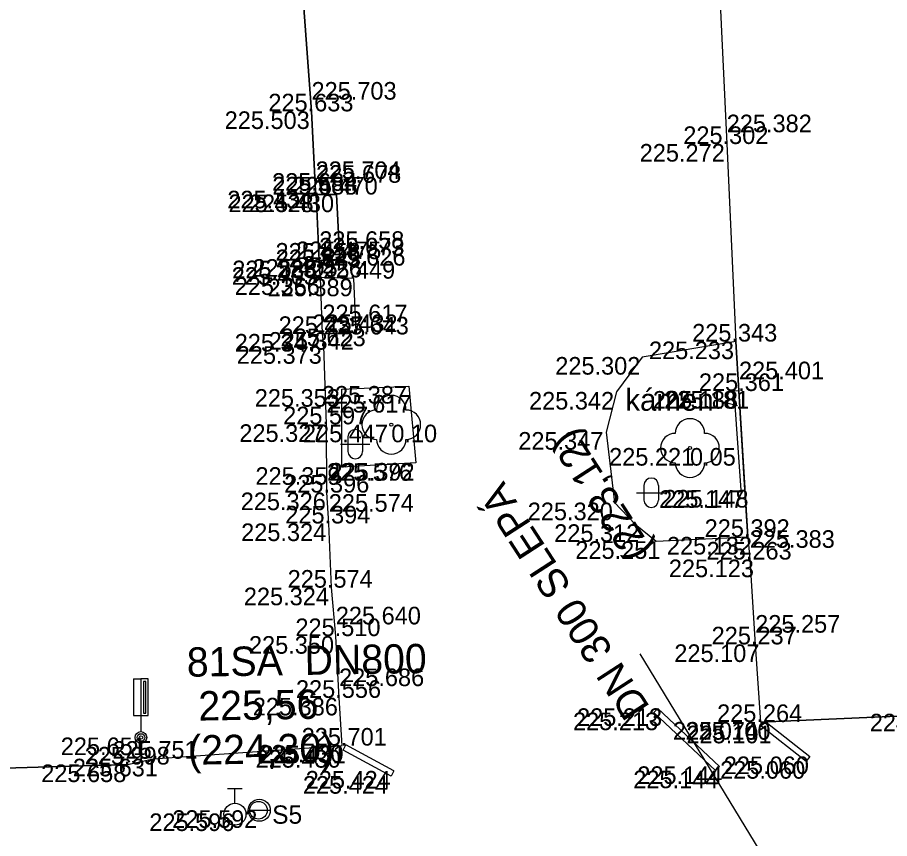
# Model space of a CAD drawing. Extents: x -599516 to -599132, y -1163668 to -1163119.
# Drawn here: x -599368.79 to -599353.92, y -1163367.41 to -1163353.41 of the extents above; entities that cross this region are included whole.
import ezdxf

# ---------------------------------------------------------------- set-up
doc = ezdxf.new("R2010")
doc.units = 0
for name, color, linetype in [('Bod-oznac1', 7, 'Continuous'), ('Bod-oznac2', 7, 'Continuous'), ('Bod-oznac3', 7, 'Continuous'), ('Bod-vyska1', 7, 'Continuous'), ('Bod-vyska2', 7, 'Continuous'), ('Bod-vyska3', 7, 'Continuous'), ('Z_cela-hrobu-dolni-linie', 7, 'Continuous'), ('Z_cela-hrobu-horni-linie', 7, 'Continuous'), ('Z_kanalizace-destova', 7, 'Continuous'), ('Z_komunikace', 7, 'Continuous'), ('Z_kultury-znacky', 7, 'Continuous'), ('Z_nove-stromy-prumer-kmene', 7, 'Continuous'), ('Z_obvod-skruze', 7, 'Continuous'), ('Z_obvod-skruze-cislo-foto', 7, 'Continuous'), ('Z_popis-budov-povrchu', 7, 'Continuous'), ('Z_stromy-nove-vysazene', 7, 'Continuous'), ('Z_voda-znacky-hydrant', 7, 'Continuous'), ('Z_vodovod-bez-rozliseni', 7, 'Continuous'), ('Z_vol-lin-obrubnik', 7, 'Continuous'), ('Z_vol-lin-odkazova-cara', 7, 'Continuous'), ('Z_znacky-ostatni-orientacni-sloupek', 7, 'Continuous'), ('Z_znacky-ostatni-skruz', 7, 'Continuous'), ('Z_zpevnene-plochy', 7, 'Continuous')]:
    doc.layers.add(name, color=color, linetype=linetype)

msp = doc.modelspace()

# ---------------------------------------------------------------- linework, layer by layer
at = {"layer": 'Bod-oznac1'}
for p, q in [((-599363.774, -1163355.013), (-599363.774, -1163355.013)), ((-599356.698, -1163355.569), (-599356.698, -1163355.569)), ((-599363.705, -1163356.366), (-599363.705, -1163356.366)), ((-599363.695, -1163356.43), (-599363.695, -1163356.43)), ((-599363.349, -1163356.43), (-599363.349, -1163356.43)), ((-599363.289, -1163357.532), (-599363.289, -1163357.532)), ((-599363.643, -1163357.669), (-599363.643, -1163357.669)), ((-599363.642, -1163357.557), (-599363.642, -1163357.557)), ((-599363.623, -1163357.842), (-599363.623, -1163357.842)), ((-599363.052, -1163357.864), (-599363.052, -1163357.864)), ((-599363.588, -1163358.807), (-599363.588, -1163358.807)), ((-599363.011, -1163358.775), (-599363.011, -1163358.775)), ((-599363.565, -1163359.015), (-599363.565, -1163359.015)), ((-599356.541, -1163358.936), (-599356.541, -1163358.936)), ((-599358.14, -1163359.2), (-599358.14, -1163359.2)), ((-599363.259, -1163359.747), (-599363.259, -1163359.747)), ((-599362.113, -1163359.694), (-599362.113, -1163359.694)), ((-599356.578, -1163359.78), (-599356.578, -1163359.78)), ((-599356.489, -1163359.779), (-599356.489, -1163359.779)), ((-599358.574, -1163359.795), (-599358.574, -1163359.795)), ((-599363.521, -1163360.347), (-599363.521, -1163360.347)), ((-599362.414, -1163360.353), (-599362.414, -1163360.353)), ((-599358.755, -1163360.479), (-599358.755, -1163360.479)), ((-599357.324, -1163360.751), (-599357.324, -1163360.751)), ((-599363.259, -1163361.078), (-599363.259, -1163361.078)), ((-599361.997, -1163361.006), (-599361.997, -1163361.006)), ((-599363.51, -1163361.51), (-599363.51, -1163361.51)), ((-599356.459, -1163361.471), (-599356.459, -1163361.471)), ((-599356.387, -1163361.465), (-599356.387, -1163361.465)), ((-599358.609, -1163361.681), (-599358.609, -1163361.681)), ((-599363.48, -1163362.037), (-599363.48, -1163362.037)), ((-599358.26, -1163362.051), (-599358.26, -1163362.051)), ((-599356.339, -1163362.266), (-599356.339, -1163362.266)), ((-599357.9, -1163362.34), (-599357.9, -1163362.34)), ((-599356.306, -1163362.652), (-599356.306, -1163362.652)), ((-599363.434, -1163363.131), (-599363.434, -1163363.131)), ((-599363.36, -1163363.957), (-599363.36, -1163363.957)), ((-599356.213, -1163364.098), (-599356.213, -1163364.098)), ((-599363.304, -1163365.009), (-599363.304, -1163365.009)), ((-599357.939, -1163365.26), (-599357.939, -1163365.26)), ((-599357.871, -1163365.188), (-599357.871, -1163365.188)), ((-599356.121, -1163365.421), (-599356.121, -1163365.421)), ((-599356.027, -1163365.423), (-599356.027, -1163365.423)), ((-599356.112, -1163365.484), (-599356.112, -1163365.484)), ((-599366.681, -1163365.685), (-599366.681, -1163365.685)), ((-599363.252, -1163365.823), (-599363.252, -1163365.823)), ((-599363.187, -1163365.811), (-599363.187, -1163365.811)), ((-599363.235, -1163365.899), (-599363.235, -1163365.899)), ((-599355.282, -1163366.009), (-599355.282, -1163366.009)), ((-599366.91, -1163366.145), (-599366.91, -1163366.145)), ((-599366.475, -1163366.047), (-599366.475, -1163366.047)), ((-599355.344, -1163366.087), (-599355.344, -1163366.087)), ((-599362.369, -1163366.255), (-599362.369, -1163366.255)), ((-599356.89, -1163366.249), (-599356.89, -1163366.249)), ((-599356.822, -1163366.177), (-599356.822, -1163366.177)), ((-599362.417, -1163366.343), (-599362.417, -1163366.343)), ((-599365.079, -1163366.979), (-599365.079, -1163366.979)), ((-599364.677, -1163366.925), (-599364.677, -1163366.925))]:
    msp.add_line(p, q, dxfattribs=at)
at = {"layer": 'Bod-oznac2'}
for p, q in [((-599363.774, -1163355.013), (-599363.774, -1163355.013)), ((-599356.698, -1163355.569), (-599356.698, -1163355.569)), ((-599363.705, -1163356.366), (-599363.705, -1163356.366)), ((-599363.695, -1163356.43), (-599363.695, -1163356.43)), ((-599363.349, -1163356.43), (-599363.349, -1163356.43)), ((-599363.289, -1163357.532), (-599363.289, -1163357.532)), ((-599363.643, -1163357.669), (-599363.643, -1163357.669)), ((-599363.642, -1163357.557), (-599363.642, -1163357.557)), ((-599363.623, -1163357.842), (-599363.623, -1163357.842)), ((-599363.052, -1163357.864), (-599363.052, -1163357.864)), ((-599363.588, -1163358.807), (-599363.588, -1163358.807)), ((-599363.011, -1163358.775), (-599363.011, -1163358.775)), ((-599363.565, -1163359.015), (-599363.565, -1163359.015)), ((-599356.541, -1163358.936), (-599356.541, -1163358.936)), ((-599356.489, -1163359.779), (-599356.489, -1163359.779)), ((-599363.521, -1163360.347), (-599363.521, -1163360.347)), ((-599363.51, -1163361.51), (-599363.51, -1163361.51)), ((-599363.48, -1163362.037), (-599363.48, -1163362.037)), ((-599356.339, -1163362.266), (-599356.339, -1163362.266)), ((-599356.306, -1163362.652), (-599356.306, -1163362.652)), ((-599363.434, -1163363.131), (-599363.434, -1163363.131)), ((-599363.36, -1163363.957), (-599363.36, -1163363.957)), ((-599356.213, -1163364.098), (-599356.213, -1163364.098)), ((-599363.304, -1163365.009), (-599363.304, -1163365.009)), ((-599356.121, -1163365.421), (-599356.121, -1163365.421)), ((-599363.252, -1163365.823), (-599363.252, -1163365.823)), ((-599366.91, -1163366.145), (-599366.91, -1163366.145)), ((-599366.475, -1163366.047), (-599366.475, -1163366.047))]:
    msp.add_line(p, q, dxfattribs=at)
at = {"layer": 'Bod-oznac3'}
for p, q in [((-599363.774, -1163355.013), (-599363.774, -1163355.013)), ((-599356.698, -1163355.569), (-599356.698, -1163355.569)), ((-599363.705, -1163356.366), (-599363.705, -1163356.366)), ((-599363.695, -1163356.43), (-599363.695, -1163356.43)), ((-599363.643, -1163357.669), (-599363.643, -1163357.669)), ((-599363.642, -1163357.557), (-599363.642, -1163357.557)), ((-599363.623, -1163357.842), (-599363.623, -1163357.842)), ((-599363.588, -1163358.807), (-599363.588, -1163358.807)), ((-599363.565, -1163359.015), (-599363.565, -1163359.015)), ((-599356.489, -1163359.779), (-599356.489, -1163359.779)), ((-599363.521, -1163360.347), (-599363.521, -1163360.347)), ((-599363.51, -1163361.51), (-599363.51, -1163361.51)), ((-599363.48, -1163362.037), (-599363.48, -1163362.037)), ((-599356.306, -1163362.652), (-599356.306, -1163362.652)), ((-599363.36, -1163363.957), (-599363.36, -1163363.957)), ((-599356.213, -1163364.098), (-599356.213, -1163364.098)), ((-599363.304, -1163365.009), (-599363.304, -1163365.009))]:
    msp.add_line(p, q, dxfattribs=at)
at = {"layer": 'Z_cela-hrobu-dolni-linie'}
for p, q in [((-599363.642, -1163357.557), (-599363.695, -1163356.43)), ((-599363.588, -1163358.807), (-599363.623, -1163357.842))]:
    msp.add_line(p, q, dxfattribs=at)
msp.add_lwpolyline([(-599356.339, -1163362.266), (-599356.387, -1163361.465), (-599356.489, -1163359.779), (-599356.541, -1163358.936)], dxfattribs=at)
at = {"layer": 'Z_cela-hrobu-horni-linie'}
for points in [[(-599357.166, -1163346.956), (-599356.949, -1163349.946), (-599356.851, -1163352.038), (-599356.826, -1163352.806), (-599356.826, -1163352.806), (-599356.698, -1163355.569), (-599356.698, -1163355.569), (-599356.541, -1163358.936), (-599356.489, -1163359.779), (-599356.489, -1163359.779), (-599356.339, -1163362.266), (-599356.306, -1163362.652), (-599356.306, -1163362.652), (-599356.213, -1163364.098), (-599356.213, -1163364.098), (-599356.121, -1163365.421), (-599352.882, -1163365.281)], [(-599363.971, -1163352.322), (-599363.774, -1163355.013), (-599363.774, -1163355.013), (-599363.705, -1163356.366), (-599363.705, -1163356.366), (-599363.695, -1163356.43), (-599363.642, -1163357.557), (-599363.643, -1163357.669), (-599363.643, -1163357.669), (-599363.623, -1163357.842)], [(-599366.475, -1163366.047), (-599363.252, -1163365.823), (-599363.304, -1163365.009), (-599363.304, -1163365.009), (-599363.36, -1163363.957), (-599363.36, -1163363.957), (-599363.434, -1163363.131), (-599363.48, -1163362.037), (-599363.48, -1163362.037), (-599363.51, -1163361.51), (-599363.51, -1163361.51), (-599363.521, -1163360.347), (-599363.521, -1163360.347), (-599363.565, -1163359.015), (-599363.565, -1163359.015), (-599363.588, -1163358.807), (-599363.623, -1163357.842)], [(-599366.91, -1163366.145), (-599370.15, -1163366.244), (-599370.323, -1163363.578), (-599370.323, -1163363.578), (-599370.418, -1163362.163), (-599370.418, -1163362.163), (-599370.472, -1163361.1), (-599370.472, -1163361.1), (-599370.502, -1163360.515), (-599370.502, -1163360.515), (-599370.561, -1163359.448), (-599370.561, -1163359.448)]]:
    msp.add_lwpolyline(points, dxfattribs=at)
at = {"layer": 'Z_kanalizace-destova'}
msp.add_line((-599358.181, -1163364.259), (-599355.578, -1163368.537), dxfattribs=at)
at = {"layer": 'Z_komunikace'}
for points in [[(-599363.252, -1163365.823), (-599363.304, -1163365.009), (-599363.36, -1163363.957), (-599363.434, -1163363.131), (-599363.48, -1163362.037), (-599363.51, -1163361.51), (-599363.521, -1163360.347), (-599363.565, -1163359.015), (-599363.588, -1163358.807), (-599363.011, -1163358.775), (-599363.052, -1163357.864), (-599363.623, -1163357.842), (-599363.643, -1163357.669), (-599363.642, -1163357.557), (-599363.289, -1163357.532), (-599363.349, -1163356.43), (-599363.695, -1163356.43), (-599363.705, -1163356.366), (-599363.774, -1163355.013), (-599363.971, -1163352.322)], [(-599356.826, -1163352.806), (-599356.698, -1163355.569), (-599356.541, -1163358.936), (-599358.14, -1163359.2), (-599358.574, -1163359.795), (-599358.755, -1163360.479), (-599358.609, -1163361.681), (-599358.26, -1163362.051), (-599357.9, -1163362.34), (-599356.339, -1163362.266), (-599356.306, -1163362.652), (-599356.213, -1163364.098), (-599356.121, -1163365.421)], [(-599361.997, -1163361.006), (-599363.259, -1163361.078), (-599363.259, -1163359.747), (-599362.113, -1163359.694), (-599361.997, -1163361.006)], [(-599324.435, -1163363.754), (-599325.751, -1163363.83), (-599327.615, -1163363.877), (-599330.335, -1163364.07), (-599331.708, -1163364.146), (-599331.737, -1163364.257), (-599334.303, -1163364.472), (-599334.35, -1163364.321), (-599335.66, -1163364.387), (-599336.937, -1163364.435), (-599339.713, -1163364.591), (-599341.02, -1163364.64), (-599343.847, -1163364.831), (-599343.945, -1163364.836), (-599343.946, -1163364.985), (-599344.788, -1163365.021), (-599344.785, -1163364.866), (-599344.87, -1163364.868), (-599347.665, -1163365.027), (-599349.113, -1163365.087), (-599352.375, -1163365.235), (-599352.882, -1163365.281), (-599356.121, -1163365.421)], [(-599370.15, -1163366.244), (-599366.91, -1163366.145), (-599366.475, -1163366.047), (-599363.252, -1163365.823)]]:
    msp.add_lwpolyline(points, dxfattribs=at)
at = {"layer": 'Z_kultury-znacky'}
for p, q in [((-599363.153, -1163360.559), (-599363.153, -1163360.809)), ((-599362.903, -1163360.559), (-599362.903, -1163360.809)), ((-599363.278, -1163360.684), (-599362.778, -1163360.684)), ((-599358.11, -1163361.387), (-599358.11, -1163361.637)), ((-599357.86, -1163361.387), (-599357.86, -1163361.637)), ((-599358.235, -1163361.512), (-599357.735, -1163361.512))]:
    msp.add_line(p, q, dxfattribs=at)
for centre, start, end in [((-599363.028, -1163360.559), 0, 180), ((-599363.028, -1163360.809), 180, 0), ((-599357.985, -1163361.388), 0, 180), ((-599357.985, -1163361.638), 180, 0)]:
    msp.add_arc(centre, 0.125, start, end, dxfattribs=at)
at = {"layer": 'Z_obvod-skruze'}
msp.add_circle((-599364.677, -1163366.925), 0.15, dxfattribs=at)
at = {"layer": 'Z_stromy-nove-vysazene'}
for centre in [(-599362.414, -1163360.353), (-599357.324, -1163360.751)]:
    msp.add_circle(centre, 0.025, dxfattribs=at)
for centre, start, end in [((-599362.414, -1163360.103), 0, 180), ((-599362.664, -1163360.353), 90, 270), ((-599362.164, -1163360.353), 270, 90), ((-599357.324, -1163360.501), 0, 180), ((-599357.574, -1163360.751), 90, 270), ((-599357.074, -1163360.751), 270, 90), ((-599362.414, -1163360.603), 180, 0), ((-599357.324, -1163361.001), 180, 0)]:
    msp.add_arc(centre, 0.25, start, end, dxfattribs=at)
at = {"layer": 'Z_voda-znacky-hydrant'}
for p, q in [((-599365.204, -1163366.554), (-599364.954, -1163366.554)), ((-599365.079, -1163366.804), (-599365.079, -1163366.554))]:
    msp.add_line(p, q, dxfattribs=at)
msp.add_circle((-599365.079, -1163366.992), 0.188, dxfattribs=at)
at = {"layer": 'Z_vol-lin-obrubnik'}
for p, q in [((-599356.822, -1163366.177), (-599357.871, -1163365.188)), ((-599362.369, -1163366.255), (-599363.187, -1163365.811))]:
    msp.add_line(p, q, dxfattribs=at)
for points in [[(-599356.822, -1163366.177), (-599356.89, -1163366.249), (-599357.939, -1163365.26), (-599357.871, -1163365.188)], [(-599356.027, -1163365.423), (-599356.112, -1163365.484), (-599355.344, -1163366.087)], [(-599356.027, -1163365.423), (-599355.282, -1163366.009), (-599355.344, -1163366.087)], [(-599362.369, -1163366.255), (-599362.417, -1163366.343), (-599363.235, -1163365.899), (-599363.187, -1163365.811)]]:
    msp.add_lwpolyline(points, dxfattribs=at)
at = {"layer": 'Z_vol-lin-odkazova-cara'}
msp.add_line((-599356.512, -1163360.032), (-599356.884, -1163359.942), dxfattribs=at)
at = {"layer": 'Z_znacky-ostatni-orientacni-sloupek'}
for p, q in [((-599366.806, -1163364.685), (-599366.806, -1163365.31)), ((-599366.806, -1163364.685), (-599366.681, -1163364.685)), ((-599366.806, -1163365.31), (-599366.681, -1163365.31)), ((-599366.681, -1163365.31), (-599366.681, -1163365.585))]:
    msp.add_line(p, q, dxfattribs=at)
for points in [[(-599366.681, -1163365.31), (-599366.556, -1163365.31), (-599366.556, -1163364.685), (-599366.681, -1163364.685)], [(-599366.639, -1163365.268), (-599366.598, -1163365.268), (-599366.598, -1163364.728), (-599366.639, -1163364.728)]]:
    msp.add_lwpolyline(points, close=True, dxfattribs=at)
for radius in [0.1, 0.065, 0.03]:
    msp.add_circle((-599366.681, -1163365.685), radius, dxfattribs=at)
at = {"layer": 'Z_znacky-ostatni-skruz'}
msp.add_line((-599364.852, -1163366.925), (-599364.477, -1163366.925), dxfattribs=at)
msp.add_circle((-599364.664, -1163366.925), 0.188, dxfattribs=at)
at = {"layer": 'Z_zpevnene-plochy'}
for p, q in [((-599363.289, -1163357.532), (-599363.642, -1163357.557)), ((-599363.588, -1163358.807), (-599363.623, -1163357.842))]:
    msp.add_line(p, q, dxfattribs=at)
for points in [[(-599363.642, -1163357.557), (-599363.695, -1163356.43), (-599363.349, -1163356.43), (-599363.289, -1163357.532)], [(-599363.588, -1163358.807), (-599363.011, -1163358.775), (-599363.052, -1163357.864), (-599363.623, -1163357.842)], [(-599356.489, -1163359.779), (-599356.578, -1163359.78), (-599356.459, -1163361.471), (-599356.387, -1163361.465)]]:
    msp.add_lwpolyline(points, dxfattribs=at)

# ---------------------------------------------------------------- texts
at = {"layer": 'Bod-vyska1'}
for s, p in [('225.503', (-599365.254, -1163355.313)), ('225.272', (-599358.181, -1163355.869)), ('225.434', (-599365.209, -1163356.666)), ('225.428', (-599365.188, -1163356.73)), ('225.430', (-599364.84, -1163356.73)), ('225.388', (-599365.124, -1163357.857)), ('225.405', (-599364.78, -1163357.832)), ('225.403', (-599365.134, -1163357.969)), ('225.366', (-599365.082, -1163358.142)), ('225.389', (-599364.522, -1163358.164)), ('225.347', (-599365.083, -1163359.107)), ('225.342', (-599364.504, -1163359.075)), ('225.373', (-599365.048, -1163359.315)), ('225.233', (-599358.023, -1163359.236)), ('225.302', (-599359.62, -1163359.5)), ('225.353', (-599364.741, -1163360.047)), ('225.387', (-599363.596, -1163359.994)), ('225.188', (-599357.956, -1163360.08)), ('225.181', (-599357.763, -1163360.079)), ('225.342', (-599360.067, -1163360.095)), ('225.327', (-599365.004, -1163360.647)), ('225.447', (-599363.92, -1163360.653)), ('225.347', (-599360.25, -1163360.779)), ('225.221', (-599358.702, -1163361.051)), ('225.359', (-599364.729, -1163361.378)), ('225.392', (-599363.467, -1163361.306)), ('225.326', (-599364.98, -1163361.81)), ('225.147', (-599357.85, -1163361.771)), ('225.148', (-599357.776, -1163361.765)), ('225.320', (-599360.089, -1163361.981)), ('225.324', (-599364.973, -1163362.337)), ('225.312', (-599359.638, -1163362.351)), ('225.132', (-599357.717, -1163362.566)), ('225.251', (-599359.278, -1163362.64)), ('225.123', (-599357.684, -1163362.952)), ('225.324', (-599364.927, -1163363.431)), ('225.350', (-599364.84, -1163364.257)), ('225.107', (-599357.591, -1163364.398)), ('225.386', (-599364.774, -1163365.309)), ('225.213', (-599359.317, -1163365.56)), ('225.213', (-599359.249, -1163365.488)), ('224.951', (-599354.26, -1163365.581)), ('225.074', (-599357.614, -1163365.721)), ('225.100', (-599357.401, -1163365.723)), ('225.101', (-599357.384, -1163365.784)), ('225.651', (-599368.047, -1163365.985)), ('225.430', (-599364.678, -1163366.111)), ('225.431', (-599364.641, -1163366.123)), ('225.430', (-599364.726, -1163366.199)), ('225.060', (-599356.748, -1163366.309)), ('225.658', (-599368.38, -1163366.445)), ('225.631', (-599367.841, -1163366.347)), ('225.144', (-599358.222, -1163366.477)), ('225.060', (-599356.81, -1163366.387)), ('225.424', (-599363.873, -1163366.555)), ('225.144', (-599358.29, -1163366.549)), ('225.424', (-599363.921, -1163366.643)), ('225.596', (-599366.538, -1163367.279)), ('225.592', (-599366.147, -1163367.225))]:
    msp.add_text(s, height=0.3, dxfattribs=at).set_placement(p)
at = {"layer": 'Bod-vyska2'}
for s, p in [('225.633', (-599364.509, -1163355.013)), ('225.302', (-599357.438, -1163355.569)), ('225.684', (-599364.446, -1163356.366)), ('225.488', (-599364.441, -1163356.43)), ('225.470', (-599364.095, -1163356.43)), ('225.458', (-599364.388, -1163357.557)), ('225.475', (-599364.036, -1163357.532)), ('225.643', (-599364.384, -1163357.669)), ('225.426', (-599364.364, -1163357.842)), ('225.449', (-599363.798, -1163357.864)), ('225.437', (-599364.335, -1163358.807)), ('225.432', (-599363.757, -1163358.775)), ('225.623', (-599364.3, -1163359.015)), ('225.343', (-599357.287, -1163358.936)), ('225.361', (-599357.172, -1163359.779)), ('225.597', (-599364.257, -1163360.347)), ('225.396', (-599364.239, -1163361.51)), ('225.394', (-599364.221, -1163362.037)), ('225.392', (-599357.074, -1163362.266)), ('225.263', (-599357.041, -1163362.652)), ('225.574', (-599364.181, -1163363.131)), ('225.510', (-599364.048, -1163363.957)), ('225.237', (-599356.955, -1163364.098)), ('225.556', (-599364.039, -1163365.009)), ('225.264', (-599356.862, -1163365.421)), ('225.701', (-599363.941, -1163365.823)), ('225.998', (-599367.639, -1163366.145)), ('225.751', (-599367.165, -1163366.047))]:
    msp.add_text(s, height=0.3, dxfattribs=at).set_placement(p)
at = {"layer": 'Bod-vyska3'}
for s, p in [('225.703', (-599363.774, -1163354.813)), ('225.382', (-599356.698, -1163355.369)), ('225.704', (-599363.705, -1163356.166)), ('225.678', (-599363.695, -1163356.23)), ('225.658', (-599363.642, -1163357.357)), ('225.673', (-599363.643, -1163357.469)), ('225.626', (-599363.623, -1163357.642)), ('225.617', (-599363.588, -1163358.607)), ('225.643', (-599363.565, -1163358.815)), ('225.401', (-599356.489, -1163359.579)), ('225.617', (-599363.521, -1163360.147)), ('225.576', (-599363.51, -1163361.31)), ('225.574', (-599363.48, -1163361.837)), ('225.383', (-599356.306, -1163362.452)), ('225.640', (-599363.36, -1163363.757)), ('225.257', (-599356.213, -1163363.898)), ('225.686', (-599363.304, -1163364.809))]:
    msp.add_text(s, height=0.3, dxfattribs=at).set_placement(p)
at = {"layer": 'Z_kanalizace-destova'}
for s, p in [('(223,12)', (-599357.956, -1163362.472)), ('DN 300 SLEPÁ', (-599357.997, -1163365.168))]:
    msp.add_text(s, height=0.5, rotation=122.9508, dxfattribs=at).set_placement(p)
at = {"layer": 'Z_nove-stromy-prumer-kmene'}
for s, p in [('0.10', (-599362.414, -1163360.653)), ('0.05', (-599357.324, -1163361.051))]:
    msp.add_text(s, height=0.3, dxfattribs=at).set_placement(p)
at = {"layer": 'Z_obvod-skruze-cislo-foto'}
msp.add_text('S5', height=0.3125, dxfattribs=at).set_placement((-599364.444, -1163367.155))
at = {"layer": 'Z_popis-budov-povrchu'}
msp.add_text('kámen', height=0.375, dxfattribs=at).set_placement((-599358.425, -1163360.116))
at = {"layer": 'Z_vodovod-bez-rozliseni'}
for s, p in [('81SA  DN800', (-599365.895, -1163364.65)), (' 225,56', (-599365.884, -1163365.4)), ('(224,30) ', (-599365.872, -1163366.15))]:
    msp.add_text(s, height=0.5, rotation=0.8872, dxfattribs=at).set_placement(p)

doc.saveas('drawing.dxf')
